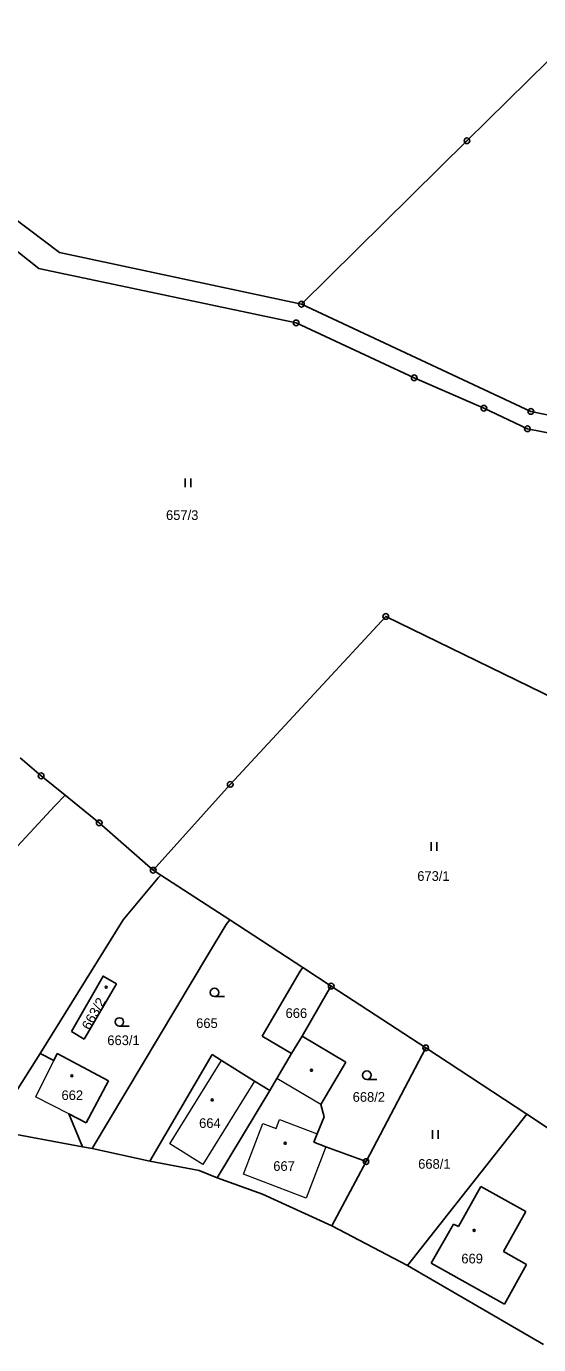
# Model space of a CAD drawing. Extents: x -727701 to -724405, y -960481 to -957284.
# Drawn here: x -726351.1 to -726261, y -958827.2 to -958595.3 of the extents above; entities that cross this region are included whole.
import ezdxf
from ezdxf.enums import TextEntityAlignment as Align

# ---------------------------------------------------------------- set-up
doc = ezdxf.new("R2010")
doc.units = 0
doc.header["$LTSCALE"] = 0.68
for name, color, linetype, lineweight in [('1', 7, 'Continuous', 25), ('3', 7, 'Continuous', 25), ('4', 7, 'Continuous', 13), ('5', 7, 'Continuous', 25), ('8', 7, 'Continuous', 25)]:
    doc.layers.add(name, color=color, linetype=linetype, lineweight=lineweight)
doc.layers.add('2', color=7, linetype='Continuous')

msp = doc.modelspace()

# ---------------------------------------------------------------- linework, layer by layer
at = {"layer": '1'}
for p, q in [((-726273.58, -958615.43), (-726231.71, -958574.16)), ((-726345.25, -958635.09), (-726395.89, -958596.87)), ((-726398.37, -958598.72), (-726348.84, -958637.9)), ((-726302.68, -958644.18), (-726273.58, -958615.43)), ((-726345.25, -958635.09), (-726302.68, -958644.18)), ((-726348.84, -958637.9), (-726347.5, -958638.16)), ((-726347.5, -958638.16), (-726303.62, -958647.46)), ((-726302.68, -958644.18), (-726262.34, -958663.04)), ((-726303.62, -958647.46), (-726282.86, -958657.12)), ((-726282.86, -958657.12), (-726270.61, -958662.47)), ((-726270.61, -958662.47), (-726262.96, -958666.08)), ((-726262.34, -958663.04), (-726234.11, -958668.79)), ((-726262.96, -958666.08), (-726258.14, -958667.06)), ((-726315.2, -958728.63), (-726287.85, -958699.1)), ((-726287.85, -958699.1), (-726253.27, -958715.95)), ((-726352.17, -958723.98), (-726348.47, -958727.13)), ((-726348.47, -958727.13), (-726344.24, -958730.56)), ((-726328.75, -958743.73), (-726315.2, -958728.63)), ((-726346.06, -958732.41), (-726344.24, -958730.56)), ((-726344.24, -958730.56), (-726338.24, -958735.41)), ((-726373.14, -958761.55), (-726346.06, -958732.41)), ((-726338.24, -958735.41), (-726328.75, -958743.73)), ((-726327.88, -958745.1), (-726334.06, -958752.48)), ((-726328.75, -958743.73), (-726327.42, -958744.59)), ((-726327.42, -958744.59), (-726327.88, -958745.1)), ((-726327.42, -958744.59), (-726315.28, -958752.44)), ((-726334.06, -958752.48), (-726348.62, -958775.95)), ((-726315.92, -958753.3), (-726319.03, -958758.43)), ((-726315.92, -958753.3), (-726315.28, -958752.44)), ((-726315.28, -958752.44), (-726302.46, -958760.83)), ((-726319.03, -958758.43), (-726339.47, -958792.68)), ((-726302.93, -958761.49), (-726309.61, -958772.9)), ((-726302.93, -958761.49), (-726302.46, -958760.83)), ((-726302.46, -958760.83), (-726297.44, -958764.12)), ((-726340.92, -958773.46), (-726335.2, -958763.74)), ((-726298.03, -958765.07), (-726302.58, -958772.92)), ((-726298.03, -958765.07), (-726297.44, -958764.12)), ((-726297.44, -958764.12), (-726280.84, -958774.98)), ((-726343.15, -958772.13), (-726340.92, -958773.46)), ((-726309.61, -958772.9), (-726304.41, -958776)), ((-726302.58, -958772.92), (-726304.41, -958776)), ((-726302.58, -958772.92), (-726294.86, -958777.52)), ((-726280.84, -958774.98), (-726291.33, -958794.97)), ((-726280.84, -958774.98), (-726263.05, -958786.62)), ((-726354.38, -958785.06), (-726348.62, -958775.95)), ((-726348.62, -958775.95), (-726346.24, -958777.21)), ((-726345.62, -958775.98), (-726346.24, -958777.21)), ((-726336.6, -958780.76), (-726345.62, -958775.98)), ((-726318.41, -958776.17), (-726329.34, -958794.9)), ((-726316.72, -958777.22), (-726318.41, -958776.17)), ((-726310.92, -958780.82), (-726316.72, -958777.22)), ((-726304.41, -958776), (-726306.99, -958780.34)), ((-726294.86, -958777.52), (-726299.27, -958784.94)), ((-726336.6, -958780.76), (-726340.53, -958788.19)), ((-726308.27, -958782.46), (-726317.5, -958797.83)), ((-726308.27, -958782.46), (-726310.92, -958780.82)), ((-726306.99, -958780.34), (-726308.27, -958782.46)), ((-726343.6, -958786.61), (-726341.19, -958792.36)), ((-726340.53, -958788.19), (-726343.6, -958786.61)), ((-726298.71, -958787.1), (-726299.92, -958790.11)), ((-726299.27, -958784.94), (-726298.71, -958787.1)), ((-726263.05, -958786.62), (-726284.06, -958813.27)), ((-726263.05, -958786.62), (-726253.58, -958792.99)), ((-726357.15, -958789.43), (-726341.19, -958792.36)), ((-726299.92, -958790.11), (-726300.49, -958791.58)), ((-726300.49, -958791.58), (-726298.42, -958792.38)), ((-726341.19, -958792.36), (-726339.47, -958792.68)), ((-726339.47, -958792.68), (-726329.34, -958794.9)), ((-726298.42, -958792.38), (-726291.33, -958794.97)), ((-726329.34, -958794.9), (-726320.7, -958796.58)), ((-726291.33, -958794.97), (-726297.32, -958806.26)), ((-726320.7, -958796.58), (-726317.5, -958797.83)), ((-726317.5, -958797.83), (-726309.56, -958800.74)), ((-726309.56, -958800.74), (-726297.32, -958806.26)), ((-726275.07, -958806.39), (-726271.13, -958799.36)), ((-726271.13, -958799.36), (-726263.23, -958803.79)), ((-726263.23, -958803.79), (-726267.17, -958810.81)), ((-726297.32, -958806.26), (-726284.06, -958813.27)), ((-726279.9, -958812.84), (-726275.93, -958806)), ((-726275.93, -958806), (-726275.07, -958806.39)), ((-726267.17, -958810.81), (-726263.09, -958813.1)), ((-726284.06, -958813.27), (-726260.12, -958827.18)), ((-726266.99, -958820.07), (-726279.9, -958812.84)), ((-726263.09, -958813.1), (-726266.99, -958820.07))]:
    msp.add_line(p, q, dxfattribs=at)
msp.add_lwpolyline([(-726335.2, -958763.74), (-726337.57, -958762.34), (-726343.15, -958772.13)], dxfattribs=at)
at = {"layer": '3'}
for p, q in [((-726323.161, -958676.33), (-726323.161, -958674.83)), ((-726322.16, -958676.33), (-726322.16, -958674.83)), ((-726279.891, -958740.31), (-726279.891, -958738.81)), ((-726278.89, -958740.31), (-726278.89, -958738.81)), ((-726317.973, -958765.97), (-726316.223, -958765.97)), ((-726334.703, -958771.17), (-726332.953, -958771.17)), ((-726291.173, -958780.53), (-726289.423, -958780.53)), ((-726279.671, -958790.96), (-726279.671, -958789.46)), ((-726278.67, -958790.96), (-726278.67, -958789.46))]:
    msp.add_line(p, q, dxfattribs=at)
for centre in [(-726317.9729, -958765.2198), (-726334.7029, -958770.4198), (-726291.1729, -958779.7798)]:
    msp.add_circle(centre, 0.75, dxfattribs=at)
at = {"layer": '4'}
for p, q in [((-726346.24, -958777.21), (-726349.47, -958783.58)), ((-726325.82, -958791.88), (-726316.72, -958777.22)), ((-726310.92, -958780.82), (-726320.02, -958795.48)), ((-726299.27, -958784.94), (-726306.99, -958780.34)), ((-726343.6, -958786.61), (-726349.47, -958783.58)), ((-726309.46, -958788.26), (-726307.12, -958789.15)), ((-726307.12, -958789.15), (-726306.52, -958787.59)), ((-726306.52, -958787.59), (-726299.92, -958790.11)), ((-726320.02, -958795.48), (-726325.82, -958791.88)), ((-726298.42, -958792.38), (-726301.87, -958801.39))]:
    msp.add_line(p, q, dxfattribs=at)
msp.add_lwpolyline([(-726301.87, -958801.39), (-726312.87, -958797.18), (-726309.46, -958788.26)], dxfattribs=at)
at = {"layer": '5'}
for centre in [(-726337.0168, -958764.3192), (-726343.0468, -958779.8792), (-726300.9268, -958778.9292), (-726318.3768, -958784.1492), (-726305.5368, -958791.7692), (-726272.3268, -958807.0792)]:
    msp.add_circle(centre, 0.175, dxfattribs=at)
at = {"layer": '8'}
for centre, radius in [((-726273.58, -958615.4299), 0.5), ((-726273.58, -958615.4299), 0.0303), ((-726302.68, -958644.1799), 0.5), ((-726302.68, -958644.1799), 0.0303), ((-726303.62, -958647.4599), 0.5), ((-726303.62, -958647.4599), 0.0303), ((-726282.86, -958657.1199), 0.5), ((-726282.86, -958657.1199), 0.0303), ((-726270.61, -958662.4699), 0.5), ((-726270.61, -958662.4699), 0.0303), ((-726262.34, -958663.0399), 0.5), ((-726262.34, -958663.0399), 0.0303), ((-726262.96, -958666.0799), 0.5), ((-726262.96, -958666.0799), 0.0303), ((-726287.85, -958699.0999), 0.5), ((-726287.85, -958699.0999), 0.0303), ((-726348.47, -958727.1299), 0.5), ((-726348.47, -958727.1299), 0.0303), ((-726315.2, -958728.6299), 0.5), ((-726315.2, -958728.6299), 0.0303), ((-726338.24, -958735.4099), 0.5), ((-726338.24, -958735.4099), 0.0303), ((-726328.75, -958743.7299), 0.5), ((-726328.75, -958743.7299), 0.0303), ((-726297.44, -958764.1199), 0.5), ((-726297.44, -958764.1199), 0.0303), ((-726280.84, -958774.9799), 0.5), ((-726280.84, -958774.9799), 0.0303), ((-726291.33, -958794.9699), 0.5), ((-726291.33, -958794.9699), 0.0303)]:
    msp.add_circle(centre, radius, dxfattribs=at)

# ---------------------------------------------------------------- texts
at = {"layer": '2'}
for s, p in [('657/3', (-726326.5, -958682.125)), ('673/1', (-726282.32, -958745.605)), ('665', (-726321.2, -958771.485)), ('663/1', (-726336.82, -958774.495)), ('662', (-726344.88, -958784.155)), ('668/2', (-726293.68, -958784.465)), ('664', (-726320.68, -958789.065)), ('667', (-726307.64, -958796.615)), ('668/1', (-726282.16, -958796.245)), ('669', (-726274.57, -958812.895))]:
    msp.add_text(s, height=1.7, dxfattribs=at).set_placement(p)
at = {"layer": '2', "width": 1.05}
msp.add_text('663/2', height=1.7, rotation=61, dxfattribs=at).set_placement((-726339.938, -958771.976))
at = {"layer": '2'}
msp.add_text('666', height=1.7, dxfattribs=at).set_placement((-726303.579, -958769.715), align=Align.CENTER)

doc.saveas('drawing.dxf')
